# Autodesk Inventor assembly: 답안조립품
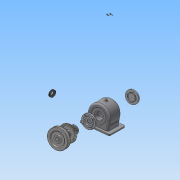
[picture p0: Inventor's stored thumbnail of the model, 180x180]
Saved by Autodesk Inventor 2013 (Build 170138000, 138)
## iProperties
Created: 2015-09
Part Number: 답안조립품
Document SubType Name: Assembly
Designer: ST3
Author: ST3
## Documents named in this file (14)
- C:\Users\ST3\Desktop\450907V1005\답안조립품.iam
- C:\Users\ST3\Desktop\450907V1005\V-벨트풀리.ipt
- C:\Users\ST3\Desktop\450907V1005\뒤커버.ipt
- C:\Users\ST3\Desktop\450907V1005\멈춤나사 - M4x10.ipt
- C:\Users\ST3\Desktop\450907V1005\베어링 6203.ipt
- C:\Users\ST3\Desktop\450907V1005\본체.ipt
- C:\Users\ST3\Desktop\450907V1005\볼트 M3 x 8.ipt
- C:\Users\ST3\Desktop\450907V1005\볼트 M3 x 10.ipt
- C:\Users\ST3\Desktop\450907V1005\스퍼기어.ipt
- C:\Users\ST3\Desktop\450907V1005\앞커버.ipt
- C:\Users\ST3\Desktop\450907V1005\오일 실 17 32 8.ipt
- C:\Users\ST3\Desktop\450907V1005\축.ipt
- C:\Users\ST3\Desktop\450907V1005\키 - 5 x 5 x 18.ipt
- C:\Users\ST3\Desktop\450907V1005\키 - 6 x 6 x 22.ipt
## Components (3 placed, 3 different names)
1. V-벨트풀리:1
2. ISO 4762 M3 x 8:1
3. ISO 4762 M3 x 10:1
